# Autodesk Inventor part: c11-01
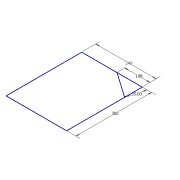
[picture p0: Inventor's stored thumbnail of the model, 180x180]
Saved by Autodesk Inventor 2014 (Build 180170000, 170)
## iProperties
Created: 2011-01
Part Number: c11-01
Material: Generic
Document SubType Name: Sheet Metal
Designer: Thom Tremblay
Density: 1 g/cm^3
Sheet Metal Rule: Default_mm
Appearance: Generic
Author: Thom Tremblay
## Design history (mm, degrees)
sketch "Sketch1"
  geometry: L1 (0, 0)-(240, 0); L2 (240, 0)-(240, 300); L3 (240, 300)-(0, 300); L4 (0, 300)-(0, 0); L5 (140, 300)-(240, 229.979)
  constraints: 10 end point, 2 parallel, 2 point on line, 1 horizontal, 1 perpendicular
  dimensions: "d0" = 240 distance of L3.end L2.end; "d1" = 300 distance of L2.end L1.end; "d2" = 35 deg angle of L3 L5; "d3" = 100 distance from line of L2 L5.start
other parameters: "Thickness" = 0.5 (derived), "BendRadius" = 0.5 (= Thickness), "BendReliefWidth" = 0.5 (= Thickness), "BendReliefDepth" = 0.25 (= 0.5 x Thickness), "CornerReliefSize" = 2 (= 4 x Thickness), "SeamGap" = 0.01, "MinimumRemnant" = 1 (= 2 x Thickness), "TransitionRadius" = 0.5 (= BendRadius), "JacobiRadiusSize" = 0.5 (= BendRadius), "GapSize" = 0.5 (= Thickness)
